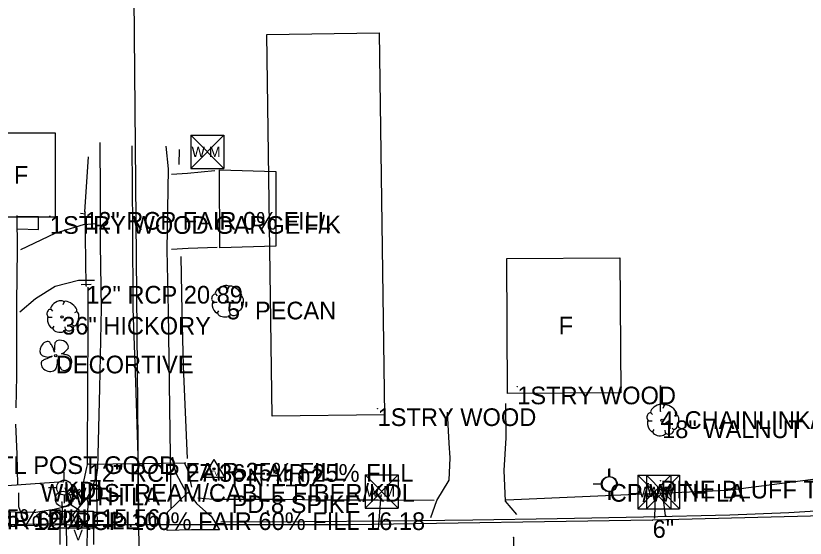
# Model space of a CAD drawing. Extents: x 1304270 to 1306561, y 1876019 to 1876752.
# Drawn here: x 1305592.5 to 1305816.1, y 1876418.6 to 1876566.4 of the extents above; entities that cross this region are included whole.
import ezdxf

# ---------------------------------------------------------------- set-up
doc = ezdxf.new("R2010")
doc.units = 0
for name, color, linetype in [('S_BUILDING', 7, 'Continuous'), ('S_BUILDING_ANNOT', 7, 'Continuous'), ('S_CROSS_DRAIN', 7, 'Continuous'), ('S_CROSS_DRAIN_ANNOT', 7, 'Continuous'), ('S_DITCHLINE', 7, 'Continuous'), ('S_DRG_PT_SYM', 7, 'Continuous'), ('S_DRIVEWAY', 7, 'Continuous'), ('S_EDGE_CONCRETE', 7, 'Continuous'), ('S_EDGE_PAVEMENT', 7, 'Continuous'), ('S_FENCE', 7, 'Continuous'), ('S_FENCE_ANNOT', 7, 'Continuous'), ('S_FIBER_OPTIC_CABLE', 7, 'Continuous'), ('S_FIBER_OPTIC_CABLE_ANNOT', 7, 'Continuous'), ('S_HEADWALL', 7, 'Continuous'), ('S_MISC_STRUCTURES_ANNOT', 7, 'Continuous'), ('S_MSC_PT_SYM', 7, 'Continuous'), ('S_PAVEMENT_CROWN', 7, 'Continuous'), ('S_SANITARY_SEWER', 7, 'Continuous'), ('S_SECONDARY_CTL', 7, 'Continuous'), ('S_SECONDARY_CTL_ANNOT', 7, 'Continuous'), ('S_SHOULDER', 7, 'Continuous'), ('S_SIDE_DRAIN', 7, 'Continuous'), ('S_SIDE_DRAIN_ANNOT', 7, 'Continuous'), ('S_STR_PT_SYM', 7, 'Continuous'), ('S_SURVEY_TEXT_ANNOT', 7, 'Continuous'), ('S_TREE', 7, 'Continuous'), ('S_TREE_ANNOT', 7, 'Continuous'), ('S_UTILITY_POLE', 7, 'Continuous'), ('S_UTILITY_POLE_ANNOT', 7, 'Continuous'), ('S_UTL_PT_SYM', 7, 'Continuous'), ('S_WATER_UTILITIES', 7, 'Continuous'), ('S_WATER_UTILITIES_ANNOT', 7, 'Continuous')]:
    doc.layers.add(name, color=color, linetype=linetype)

msp = doc.modelspace()

# ---------------------------------------------------------------- linework, layer by layer
at = {"layer": 'S_BUILDING'}
for points in [[(1305695.38, 1876561.55), (1305696.88, 1876453.53), (1305665.14, 1876453.09), (1305663.64, 1876561.11)], [(1305583.2, 1876509.43), (1305583.21, 1876533.31), (1305603.68, 1876533.3), (1305603.67, 1876509.42)], [(1305731.79, 1876459.52), (1305731.52, 1876497.69), (1305763.57, 1876497.91), (1305763.84, 1876459.75)]]:
    msp.add_lwpolyline(points, close=True, dxfattribs=at)
at = {"layer": 'S_CROSS_DRAIN'}
msp.add_line((1305613.16, 1876439.55), (1305640.51, 1876439.91), dxfattribs=at)
at = {"layer": 'S_DITCHLINE'}
for points in [[(1305638.83, 1876528.57), (1305638.7, 1876524.33)], [(1305613.05, 1876526.51), (1305612, 1876510.94)], [(1305641.11, 1876441.17), (1305640.57, 1876454.2), (1305640.03, 1876467.24), (1305639.68, 1876482.75), (1305639.32, 1876498.26)], [(1305612.93, 1876489.58), (1305612.88, 1876476.34), (1305612.84, 1876463.1), (1305612.69, 1876440.08), (1305612.73, 1876439.33), (1305612.59, 1876438.62), (1305611.2, 1876432.5), (1305607.35, 1876427.64), (1305603.4, 1876426.75), (1305597.6, 1876425.74)], [(1305642.36, 1876433.06), (1305641.55, 1876437.08), (1305640.82, 1876438.78), (1305640.27, 1876439.83)]]:
    msp.add_lwpolyline(points, dxfattribs=at)
at = {"layer": 'S_DRG_PT_SYM'}
for points in [[(1305612.13, 1876510.88), (1305612.13, 1876510.93), (1305612.13, 1876510.88), (1305612.08, 1876510.88), (1305612.13, 1876510.88), (1305612.13, 1876510.83), (1305612.13, 1876510.88), (1305612.18, 1876510.88)], [(1305612.46, 1876489.97), (1305612.46, 1876490.02), (1305612.46, 1876489.97), (1305612.41, 1876489.97), (1305612.46, 1876489.97), (1305612.46, 1876489.92), (1305612.46, 1876489.97), (1305612.51, 1876489.97)], [(1305613.16, 1876439.55), (1305613.16, 1876439.6), (1305613.16, 1876439.55), (1305613.11, 1876439.55), (1305613.16, 1876439.55), (1305613.16, 1876439.5), (1305613.16, 1876439.55), (1305613.21, 1876439.55)], [(1305640.51, 1876439.91), (1305640.51, 1876439.96), (1305640.51, 1876439.91), (1305640.45, 1876439.91), (1305640.51, 1876439.91), (1305640.51, 1876439.86), (1305640.51, 1876439.91), (1305640.55, 1876439.91)], [(1305597.54, 1876425.9), (1305597.54, 1876425.95), (1305597.54, 1876425.9), (1305597.49, 1876425.9), (1305597.54, 1876425.9), (1305597.54, 1876425.85), (1305597.54, 1876425.9), (1305597.59, 1876425.9)]]:
    msp.add_lwpolyline(points, dxfattribs=at)
at = {"layer": 'S_DRIVEWAY'}
for points in [[(1305636.66, 1876521.54), (1305641.19, 1876521.88), (1305648.89, 1876522.59)], [(1305592.81, 1876509.9), (1305592.9, 1876500.39), (1305592.75, 1876485.12), (1305592.69, 1876464.5), (1305592.57, 1876455.51)], [(1305615.59, 1876507.51), (1305611.6, 1876507.24), (1305603.57, 1876504.81), (1305593.84, 1876500.18)], [(1305649.51, 1876500.8), (1305641.33, 1876500.55), (1305636.59, 1876500.27)], [(1305593.7, 1876482.62), (1305598.08, 1876486.44), (1305603.65, 1876489.87), (1305610.31, 1876491.59), (1305614.82, 1876491.57)], [(1305731.16, 1876456.66), (1305731.24, 1876447.02), (1305730.68, 1876437.76), (1305731.09, 1876429.06), (1305734.27, 1876425.27)], [(1305710.05, 1876424.49), (1305711.72, 1876429.21), (1305715.2, 1876434.98), (1305715.56, 1876441.35), (1305715.25, 1876445.5), (1305714.78, 1876454.23)], [(1305593.07, 1876433.69), (1305592.9, 1876442.34), (1305592.55, 1876450.85)], [(1305593.28, 1876431.42), (1305593.25, 1876427.54), (1305594.59, 1876423.91)]]:
    msp.add_lwpolyline(points, dxfattribs=at)
msp.add_lwpolyline([(1305650.18, 1876522.79), (1305666.13, 1876522.32), (1305666.14, 1876501.23), (1305650.34, 1876500.78)], close=True, dxfattribs=at)
at = {"layer": 'S_EDGE_CONCRETE'}
for points in [[(1305592.99, 1876506.09), (1305598.91, 1876505.92), (1305598.98, 1876509.5), (1305592.97, 1876509.58)], [(1305606.95, 1876415.73), (1305606.84, 1876422.83), (1305609.75, 1876426.4), (1305612.13, 1876429.33), (1305612.55, 1876429.88), (1305612.9, 1876428.9), (1305612.8, 1876425.2), (1305612.7, 1876421.97), (1305612.68, 1876415.16)]]:
    msp.add_lwpolyline(points, dxfattribs=at)
msp.add_lwpolyline([(1305650.19, 1876420.99), (1305642.3, 1876420.97), (1305635.39, 1876420.81), (1305635.48, 1876425.93), (1305641.29, 1876431.6), (1305643.69, 1876428.4), (1305646.34, 1876426.01), (1305647.82, 1876424.84)], close=True, dxfattribs=at)
at = {"layer": 'S_EDGE_PAVEMENT'}
for points in [[(1305615.62, 1876422.51), (1305615.36, 1876435.81), (1305615.78, 1876438.51), (1305616.3, 1876461.07), (1305616.83, 1876483.63), (1305616.55, 1876501.66), (1305616.47, 1876516.12), (1305616.39, 1876530.58)], [(1305636.55, 1876427.14), (1305636.35, 1876441.93), (1305636.05, 1876462.38), (1305635.75, 1876482.84), (1305635.35, 1876500.2), (1305635.78, 1876523.1), (1305635.13, 1876529.49)], [(1305640.77, 1876431.64), (1305639.41, 1876434.05), (1305637.97, 1876436.91), (1305637.33, 1876439), (1305636.97, 1876441.52)], [(1305612.66, 1876429.78), (1305614.03, 1876432.44), (1305615.18, 1876435.69)], [(1305650.55, 1876423.21), (1305674.32, 1876423.35), (1305698.09, 1876423.48), (1305721.97, 1876423.8), (1305745.85, 1876424.12), (1305770.29, 1876424.67), (1305794.74, 1876425.23), (1305811.42, 1876425.85), (1305825.07, 1876426.72), (1305843.96, 1876426.78), (1305860.03, 1876426.98), (1305876.09, 1876427.18), (1305883.24, 1876427.59), (1305898.06, 1876427.36), (1305904.05, 1876427.05), (1305918.23, 1876426.76), (1305933.32, 1876426.78)], [(1305388.38, 1876420.94), (1305412.9, 1876420.99), (1305437.42, 1876421.04), (1305451.62, 1876420.93), (1305465.15, 1876420.97), (1305478.67, 1876421.01), (1305492.19, 1876421.05), (1305505.71, 1876421.09), (1305520.11, 1876421.2), (1305523.54, 1876421.95), (1305534.76, 1876421.53), (1305559.32, 1876421.96), (1305583.88, 1876422.38), (1305606.66, 1876422.73)], [(1305612.81, 1876422.22), (1305627.2, 1876422.52), (1305635.24, 1876422.4)]]:
    msp.add_lwpolyline(points, dxfattribs=at)
at = {"layer": 'S_FENCE'}
msp.add_line((1305775.05, 1876454.52), (1305775.11, 1876461.74), dxfattribs=at)
msp.add_lwpolyline([(1305775.05, 1876454.52), (1305775.11, 1876461.74)], dxfattribs=at)
msp.add_lwpolyline([(1305775.05, 1876454.52), (1305775.11, 1876461.74)], dxfattribs=at)
at = {"layer": 'S_FIBER_OPTIC_CABLE'}
msp.add_line((1305605.99, 1876434.57), (1305581.98, 1876432.88), dxfattribs=at)
at = {"layer": 'S_HEADWALL'}
for points in [[(1305612.27, 1876510.3), (1305610.86, 1876510.44)], [(1305613.91, 1876490.33), (1305611, 1876490.27)]]:
    msp.add_lwpolyline(points, dxfattribs=at)
at = {"layer": 'S_MSC_PT_SYM'}
for points in [[(1305602.17, 1876509.7), (1305602.17, 1876509.75), (1305602.17, 1876509.7), (1305602.12, 1876509.7), (1305602.17, 1876509.7), (1305602.17, 1876509.65), (1305602.17, 1876509.7), (1305602.22, 1876509.7)], [(1305775.11, 1876461.74), (1305775.11, 1876461.79), (1305775.11, 1876461.74), (1305775.06, 1876461.74), (1305775.11, 1876461.74), (1305775.11, 1876461.69), (1305775.11, 1876461.74), (1305775.16, 1876461.74)], [(1305775.05, 1876454.52), (1305775.05, 1876454.57), (1305775.05, 1876454.52), (1305775, 1876454.52), (1305775.05, 1876454.52), (1305775.05, 1876454.47), (1305775.05, 1876454.52), (1305775.1, 1876454.52)], [(1305775.03, 1876434.83), (1305775.03, 1876434.88), (1305775.03, 1876434.83), (1305774.98, 1876434.83), (1305775.03, 1876434.83), (1305775.03, 1876434.78), (1305775.03, 1876434.83), (1305775.08, 1876434.83)], [(1305599.66, 1876433.91), (1305599.66, 1876433.96), (1305599.66, 1876433.91), (1305599.61, 1876433.91), (1305599.66, 1876433.91), (1305599.66, 1876433.86), (1305599.66, 1876433.91), (1305599.71, 1876433.91)]]:
    msp.add_lwpolyline(points, dxfattribs=at)
at = {"layer": 'S_PAVEMENT_CROWN'}
msp.add_lwpolyline([(1305627.31, 1876423.22), (1305627.18, 1876441.92), (1305626.49, 1876462.73), (1305625.8, 1876483.54), (1305625.64, 1876506.57), (1305625.48, 1876529.6)], dxfattribs=at)
at = {"layer": 'S_SANITARY_SEWER'}
msp.add_line((1305627.46, 1876413.95), (1305625.83, 1876600.63), dxfattribs=at)
at = {"layer": 'S_SECONDARY_CTL'}
for p, q in [((1305648.63, 1876440.83), (1305645.62, 1876435.88)), ((1305648.63, 1876440.83), (1305651.58, 1876435.88)), ((1305645.62, 1876435.88), (1305651.58, 1876435.88))]:
    msp.add_line(p, q, dxfattribs=at)
for radius in [0.311, 0.183, 0.103]:
    msp.add_circle((1305648.63, 1876438.22), radius, dxfattribs=at)
at = {"layer": 'S_SHOULDER'}
for points in [[(1305731.36, 1876429.4), (1305755.14, 1876430.48), (1305774.63, 1876431.35), (1305794.11, 1876432.21), (1305818.31, 1876435.26), (1305824.04, 1876438.54)], [(1305644.05, 1876429.98), (1305648.45, 1876429.64), (1305668.23, 1876429.67), (1305679.16, 1876429.46), (1305695.09, 1876429.42), (1305711.02, 1876429.38)]]:
    msp.add_lwpolyline(points, dxfattribs=at)
at = {"layer": 'S_SIDE_DRAIN'}
for p, q in [((1305612.46, 1876489.97), (1305612.13, 1876510.88)), ((1305597.54, 1876425.9), (1305581.35, 1876426.14))]:
    msp.add_line(p, q, dxfattribs=at)
at = {"layer": 'S_STR_PT_SYM'}
for points in [[(1305734.51, 1876461.48), (1305734.51, 1876461.53), (1305734.51, 1876461.48), (1305734.46, 1876461.48), (1305734.51, 1876461.48), (1305734.51, 1876461.43), (1305734.51, 1876461.48), (1305734.56, 1876461.48)], [(1305694.97, 1876455.33), (1305694.97, 1876455.38), (1305694.97, 1876455.33), (1305694.92, 1876455.33), (1305694.97, 1876455.33), (1305694.97, 1876455.28), (1305694.97, 1876455.33), (1305695.02, 1876455.33)]]:
    msp.add_lwpolyline(points, dxfattribs=at)
at = {"layer": 'S_TREE'}
for p, q in [((1305652.84, 1876489.74), (1305652.45, 1876488.89)), ((1305649.04, 1876487.73), (1305649.54, 1876487.15)), ((1305656.4, 1876486.95), (1305655.74, 1876486.68)), ((1305606.2, 1876485.44), (1305605.81, 1876484.59)), ((1305648.38, 1876485.4), (1305649.51, 1876485.4)), ((1305602.4, 1876483.43), (1305602.9, 1876482.85)), ((1305609.76, 1876482.65), (1305609.1, 1876482.38)), ((1305649.54, 1876482.23), (1305650.01, 1876482.92)), ((1305653.23, 1876481.96), (1305653.15, 1876482.73)), ((1305655.63, 1876482.85), (1305655.16, 1876483.27)), ((1305601.74, 1876481.1), (1305602.86, 1876481.1)), ((1305602.9, 1876477.93), (1305603.37, 1876478.62)), ((1305606.58, 1876477.65), (1305606.51, 1876478.43)), ((1305608.99, 1876478.55), (1305608.52, 1876478.97)), ((1305603.48, 1876471.21), (1305603.24, 1876472.1)), ((1305605.43, 1876470.75), (1305605.81, 1876470.91)), ((1305602.83, 1876470.05), (1305601.86, 1876469.83)), ((1305604.37, 1876469.12), (1305604.45, 1876468.68)), ((1305776.08, 1876456.15), (1305775.7, 1876455.3)), ((1305772.29, 1876454.14), (1305772.79, 1876453.56)), ((1305779.65, 1876453.36), (1305778.99, 1876453.09)), ((1305771.63, 1876451.81), (1305772.75, 1876451.81)), ((1305772.79, 1876448.63), (1305773.25, 1876449.33)), ((1305776.47, 1876448.36), (1305776.39, 1876449.14)), ((1305778.87, 1876449.25), (1305778.41, 1876449.68))]:
    msp.add_line(p, q, dxfattribs=at)
for centre in [(1305652.28, 1876485.5), (1305605.64, 1876481.2), (1305603.85, 1876470.23), (1305775.53, 1876451.91)]:
    msp.add_circle(centre, 0.341, dxfattribs=at)
for centre, major_axis, ratio, start_param, end_param in [((1305650.94, 1876488.7), (1.86, 1.08), 0.471018, 0, 3.141593), ((1305654.6, 1876488.38), (-1.81, 1.36), 0.405113, 3.141593, 6.283186), ((1305648.71, 1876486.59), (0.31, 1.03), 0.646762, 0, 3.141593), ((1305655.95, 1876484.97), (0.46, 2.04), 0.482994, 3.141593, 6.283185), ((1305604.3, 1876484.4), (1.86, 1.08), 0.471018, 0, 3.141593), ((1305607.96, 1876484.08), (-1.81, 1.36), 0.405113, 3.141593, 6.283186), ((1305649.01, 1876483.94), (-0.61, 1.6), 0.420543, 6.283185, 9.424777), ((1305602.07, 1876482.29), (0.31, 1.03), 0.646762, 0, 3.141593), ((1305609.31, 1876480.67), (0.46, 2.04), 0.482994, 3.141593, 6.283185), ((1305651.48, 1876482.16), (-1.83, 0.19), 0.529943, 0, 3.141593), ((1305654.43, 1876482.45), (1.09, 0.46), 0.711534, 3.141592, 6.283185), ((1305602.37, 1876479.64), (-0.61, 1.6), 0.420543, 6.283185, 9.424777), ((1305604.83, 1876477.85), (-1.83, 0.19), 0.529943, 0, 3.141593), ((1305607.79, 1876478.15), (1.09, 0.46), 0.711534, 3.141592, 6.283185), ((1305600.96, 1876472.25), (-1.03, -1.88), 0.662338, 3.141593, 6.283185), ((1305602.62, 1876473.12), (0.62, -1.01), 0.083512, 0, 3.141593), ((1305603.55, 1876472.54), (-0.07, -1.33), 0.068203, 3.141593, 6.283185), ((1305605.51, 1876473.12), (1.89, -0.74), 0.673998, 0, 3.141593), ((1305606.39, 1876470.52), (0.96, -0.23), 0.056001, 0, 3.141593), ((1305606.61, 1876471.64), (-0.798, -0.73), 0.092159, 0, 3.141593), ((1305601.87, 1876467.57), (2.07, -0.93), 0.760068, 3.141593, 6.283185), ((1305600.28, 1876468.83), (0.477, 0.328), 0.136309, 0, 3.141593), ((1305600.9, 1876470.1), (0.964, -0.267), 0.113563, 3.141593, 6.283185), ((1305601.8, 1876469.61), (1.04, 0.44), 0.002756, 3.141593, 6.283185), ((1305604.13, 1876467.95), (0.19, 1.31), 0.114148, 3.141593, 5.822668), ((1305604.7, 1876467.91), (0.254, -0.771), 0.051603, 3.141593, 6.283185), ((1305606.47, 1876468.25), (0.88, 2.05), 0.81717, 3.141593, 6.283185), ((1305605.28, 1876466.67), (-0.321, 0.467), 0.094289, 0, 3.141593), ((1305774.19, 1876455.11), (1.86, 1.08), 0.471018, 0, 3.141593), ((1305777.84, 1876454.79), (-1.81, 1.36), 0.405113, 3.141593, 6.283186), ((1305771.95, 1876452.99), (0.31, 1.03), 0.646762, 0, 3.141593), ((1305779.2, 1876451.38), (0.46, 2.04), 0.482994, 3.141593, 6.283185), ((1305772.26, 1876450.34), (-0.61, 1.6), 0.420543, 6.283185, 9.424777), ((1305774.72, 1876448.56), (-1.83, 0.19), 0.529943, 0, 3.141593), ((1305777.68, 1876448.86), (1.09, 0.46), 0.711534, 3.141592, 6.283185)]:
    msp.add_ellipse(centre, major_axis=major_axis, ratio=ratio, start_param=start_param, end_param=end_param, dxfattribs=at)
at = {"layer": 'S_UTILITY_POLE'}
for p, q in [((1305606.24, 1876435.01), (1305606.24, 1876437.25)), ((1305760.46, 1876436.01), (1305760.46, 1876438.25)), ((1305760.7, 1876436.02), (1305760.7, 1876438.27)), ((1305604.15, 1876432.88), (1305601.82, 1876432.88)), ((1305758.36, 1876433.88), (1305756.04, 1876433.88)), ((1305758.61, 1876433.89), (1305756.28, 1876433.89)), ((1305606.32, 1876428.46), (1305606.32, 1876430.78)), ((1305760.53, 1876429.46), (1305760.53, 1876431.78)), ((1305760.78, 1876429.47), (1305760.78, 1876431.79))]:
    msp.add_line(p, q, dxfattribs=at)
for centre in [(1305606.24, 1876432.9), (1305760.46, 1876433.9), (1305760.7, 1876433.91)]:
    msp.add_circle(centre, 2.13, dxfattribs=at)
at = {"layer": 'S_UTL_PT_SYM'}
for points in [[(1305605.99, 1876434.57), (1305605.99, 1876434.62), (1305605.99, 1876434.57), (1305605.94, 1876434.57), (1305605.99, 1876434.57), (1305605.99, 1876434.52), (1305605.99, 1876434.57), (1305606.04, 1876434.57)], [(1305695.99, 1876430.82), (1305695.99, 1876430.87), (1305695.99, 1876430.82), (1305695.94, 1876430.82), (1305695.99, 1876430.82), (1305695.99, 1876430.77), (1305695.99, 1876430.82), (1305696.04, 1876430.82)], [(1305773.52, 1876430.93), (1305773.52, 1876430.98), (1305773.52, 1876430.93), (1305773.47, 1876430.93), (1305773.52, 1876430.93), (1305773.52, 1876430.88), (1305773.52, 1876430.93), (1305773.57, 1876430.93)], [(1305775.76, 1876430.97), (1305775.76, 1876431.02), (1305775.76, 1876430.97), (1305775.71, 1876430.97), (1305775.76, 1876430.97), (1305775.76, 1876430.92), (1305775.76, 1876430.97), (1305775.81, 1876430.97)], [(1305605.6, 1876428.86), (1305605.6, 1876428.91), (1305605.6, 1876428.86), (1305605.55, 1876428.86), (1305605.6, 1876428.86), (1305605.6, 1876428.81), (1305605.6, 1876428.86), (1305605.65, 1876428.86)], [(1305772.85, 1876423.7), (1305772.85, 1876423.75), (1305772.85, 1876423.7), (1305772.8, 1876423.7), (1305772.85, 1876423.7), (1305772.85, 1876423.65), (1305772.85, 1876423.7), (1305772.9, 1876423.7)], [(1305773.35, 1876424.32), (1305773.35, 1876424.37), (1305773.35, 1876424.32), (1305773.3, 1876424.32), (1305773.35, 1876424.32), (1305773.35, 1876424.27), (1305773.35, 1876424.32), (1305773.4, 1876424.32)], [(1305776.49, 1876425.01), (1305776.49, 1876425.06), (1305776.49, 1876425.01), (1305776.44, 1876425.01), (1305776.49, 1876425.01), (1305776.49, 1876424.96), (1305776.49, 1876425.01), (1305776.54, 1876425.01)], [(1305605.86, 1876422.69), (1305605.86, 1876422.74), (1305605.86, 1876422.69), (1305605.81, 1876422.69), (1305605.86, 1876422.69), (1305605.86, 1876422.64), (1305605.86, 1876422.69), (1305605.91, 1876422.69)], [(1305609.14, 1876422.38), (1305609.14, 1876422.43), (1305609.14, 1876422.38), (1305609.09, 1876422.38), (1305609.14, 1876422.38), (1305609.14, 1876422.33), (1305609.14, 1876422.38), (1305609.19, 1876422.38)], [(1305687.16, 1876422.39), (1305687.16, 1876422.44), (1305687.16, 1876422.39), (1305687.11, 1876422.39), (1305687.16, 1876422.39), (1305687.16, 1876422.34), (1305687.16, 1876422.39), (1305687.21, 1876422.39)], [(1305695.18, 1876421.13), (1305695.18, 1876421.18), (1305695.18, 1876421.13), (1305695.13, 1876421.13), (1305695.18, 1876421.13), (1305695.18, 1876421.08), (1305695.18, 1876421.13), (1305695.23, 1876421.13)], [(1305733.44, 1876418.8), (1305733.44, 1876418.85), (1305733.44, 1876418.8), (1305733.39, 1876418.8), (1305733.44, 1876418.8), (1305733.44, 1876418.75), (1305733.44, 1876418.8), (1305733.49, 1876418.8)]]:
    msp.add_lwpolyline(points, dxfattribs=at)
at = {"layer": 'S_WATER_UTILITIES'}
for p, q in [((1305642.09, 1876532.64), (1305651.43, 1876532.64)), ((1305642.09, 1876532.64), (1305642.09, 1876523.14)), ((1305642.09, 1876532.64), (1305651.43, 1876523.14)), ((1305651.43, 1876532.64), (1305642.09, 1876523.14)), ((1305651.43, 1876532.64), (1305651.43, 1876523.14)), ((1305642.09, 1876523.14), (1305651.43, 1876523.14)), ((1305691.46, 1876436.56), (1305700.8, 1876436.56)), ((1305691.46, 1876436.56), (1305691.46, 1876427.07)), ((1305691.46, 1876436.56), (1305700.8, 1876427.07)), ((1305700.8, 1876436.56), (1305691.46, 1876427.07)), ((1305700.8, 1876436.56), (1305700.8, 1876427.07)), ((1305768.66, 1876436.42), (1305778, 1876436.42)), ((1305768.66, 1876436.42), (1305768.66, 1876426.92)), ((1305768.66, 1876436.42), (1305778, 1876426.92)), ((1305778, 1876436.42), (1305768.66, 1876426.92)), ((1305771.12, 1876436.44), (1305780.46, 1876436.44)), ((1305771.12, 1876436.44), (1305771.12, 1876426.94)), ((1305771.12, 1876436.44), (1305780.46, 1876426.94)), ((1305780.46, 1876436.44), (1305771.12, 1876426.94)), ((1305778, 1876436.42), (1305778, 1876426.92)), ((1305780.46, 1876436.44), (1305780.46, 1876426.94)), ((1305607.8, 1876430.73), (1305610.63, 1876432.46)), ((1305695.18, 1876421.13), (1305695.99, 1876430.82)), ((1305773.52, 1876430.93), (1305773.35, 1876424.32)), ((1305776.49, 1876425.01), (1305775.76, 1876430.97)), ((1305605.6, 1876428.86), (1305605.86, 1876422.69)), ((1305607.68, 1876428.42), (1305610.59, 1876426.5)), ((1305605.07, 1876426.2), (1305614.48, 1876426.2)), ((1305605.07, 1876416.79), (1305605.07, 1876426.2)), ((1305614.48, 1876426.2), (1305614.48, 1876416.79)), ((1305691.46, 1876427.07), (1305700.8, 1876427.07)), ((1305768.66, 1876426.92), (1305778, 1876426.92)), ((1305771.12, 1876426.94), (1305780.46, 1876426.94)), ((1305874.58, 1876426.18), (1305772.85, 1876423.7)), ((1305772.85, 1876423.7), (1305687.16, 1876422.39)), ((1305609.14, 1876422.38), (1305577.4, 1876421.77)), ((1305605.07, 1876421.51), (1305614.48, 1876421.51)), ((1305687.16, 1876422.39), (1305609.14, 1876422.38)), ((1305733.44, 1876418.8), (1305734.26, 1876386.5))]:
    msp.add_line(p, q, dxfattribs=at)
msp.add_circle((1305605.9, 1876429.68), 2.18, dxfattribs=at)

# ---------------------------------------------------------------- texts
at = {"layer": 'S_BUILDING_ANNOT'}
for s, p in [('F', (1305592, 1876518.87)), ('F/K', (1305674.16, 1876504.83)), ('F', (1305746.24, 1876476.22)), ('1STRY WOOD', (1305734.51, 1876456.48)), ('1STRY WOOD', (1305694.97, 1876450.33))]:
    msp.add_text(s, height=5, dxfattribs=at).set_placement(p)
at = {"layer": 'S_CROSS_DRAIN_ANNOT'}
for s, p in [('12" RCP 27.36 FAIR 25% FILL', (1305613.16, 1876434.55)), ('FAIR 25% FILL', (1305640.51, 1876434.91))]:
    msp.add_text(s, height=5, dxfattribs=at).set_placement(p)
at = {"layer": 'S_FENCE_ANNOT'}
for s, p in [("4' CHAINLINK/MTL POST", (1305775.05, 1876449.52)), ("3' CHAINLINK MTL POST GOOD", (1305537.86, 1876436.76))]:
    msp.add_text(s, height=5, dxfattribs=at).set_placement(p)
at = {"layer": 'S_FIBER_OPTIC_CABLE_ANNOT'}
msp.add_text('KDL', height=5, dxfattribs=at).set_placement((1305605.99, 1876429.57))
at = {"layer": 'S_MISC_STRUCTURES_ANNOT'}
msp.add_text('PINE BLUFF TRANSIT/BUS ST STOP', height=5, dxfattribs=at).set_placement((1305775.03, 1876429.83))
at = {"layer": 'S_SECONDARY_CTL'}
msp.add_text('TV', height=1.5, rotation=360, dxfattribs=at).set_placement((1305647.42, 1876436.21))
at = {"layer": 'S_SECONDARY_CTL_ANNOT'}
for s, p in [('PN:1102', (1305653.63, 1876433.22)), ('PD:8 SPIKE', (1305653.63, 1876425.72))]:
    msp.add_text(s, height=5, dxfattribs=at).set_placement(p)
at = {"layer": 'S_SIDE_DRAIN_ANNOT'}
for s, p in [('12" RCP FAIR 0% FILL', (1305612.13, 1876505.88)), ('12" RCP 20.89', (1305612.46, 1876484.97)), ('12" RCP POOR 85% FILL 15.56', (1305537.01, 1876421.79)), ('FAIR 60% FILL', (1305581.35, 1876421.14)), ('12" RCP 100% FAIR 60% FILL 16.18', (1305597.54, 1876420.9))]:
    msp.add_text(s, height=5, dxfattribs=at).set_placement(p)
at = {"layer": 'S_SURVEY_TEXT_ANNOT'}
for s, p in [('1STRY WOOD GARGE', (1305602.17, 1876504.7)), ('WINDSTREAM/CABLE FIBER/KDL', (1305599.66, 1876428.91))]:
    msp.add_text(s, height=5, dxfattribs=at).set_placement(p)
at = {"layer": 'S_TREE_ANNOT'}
for s, p in [('5" PECAN', (1305652.28, 1876480.5)), ('36" HICKORY', (1305605.64, 1876476.2)), ('DECORTIVE', (1305603.85, 1876465.23)), ('18" WALNUT', (1305775.53, 1876446.91))]:
    msp.add_text(s, height=5, dxfattribs=at).set_placement(p)
at = {"layer": 'S_UTILITY_POLE_ANNOT'}
for s, p in [('WITH LA', (1305606.24, 1876427.9)), ('CP/WITH LA', (1305760.7, 1876428.91))]:
    msp.add_text(s, height=5, dxfattribs=at).set_placement(p)
at = {"layer": 'S_WATER_UTILITIES'}
for s, p in [('W M', (1305642.29, 1876526.4)), ('W M', (1305691.66, 1876430.33)), ('W M', (1305768.86, 1876430.18)), ('W M', (1305771.33, 1876430.2)), ('W', (1305608.62, 1876422.05)), ('V', (1305608.85, 1876417.98))]:
    msp.add_text(s, height=3, rotation=360, dxfattribs=at).set_placement(p)
at = {"layer": 'S_WATER_UTILITIES_ANNOT'}
msp.add_text('6"', height=5, dxfattribs=at).set_placement((1305772.85, 1876418.7))

doc.saveas('drawing.dxf')
